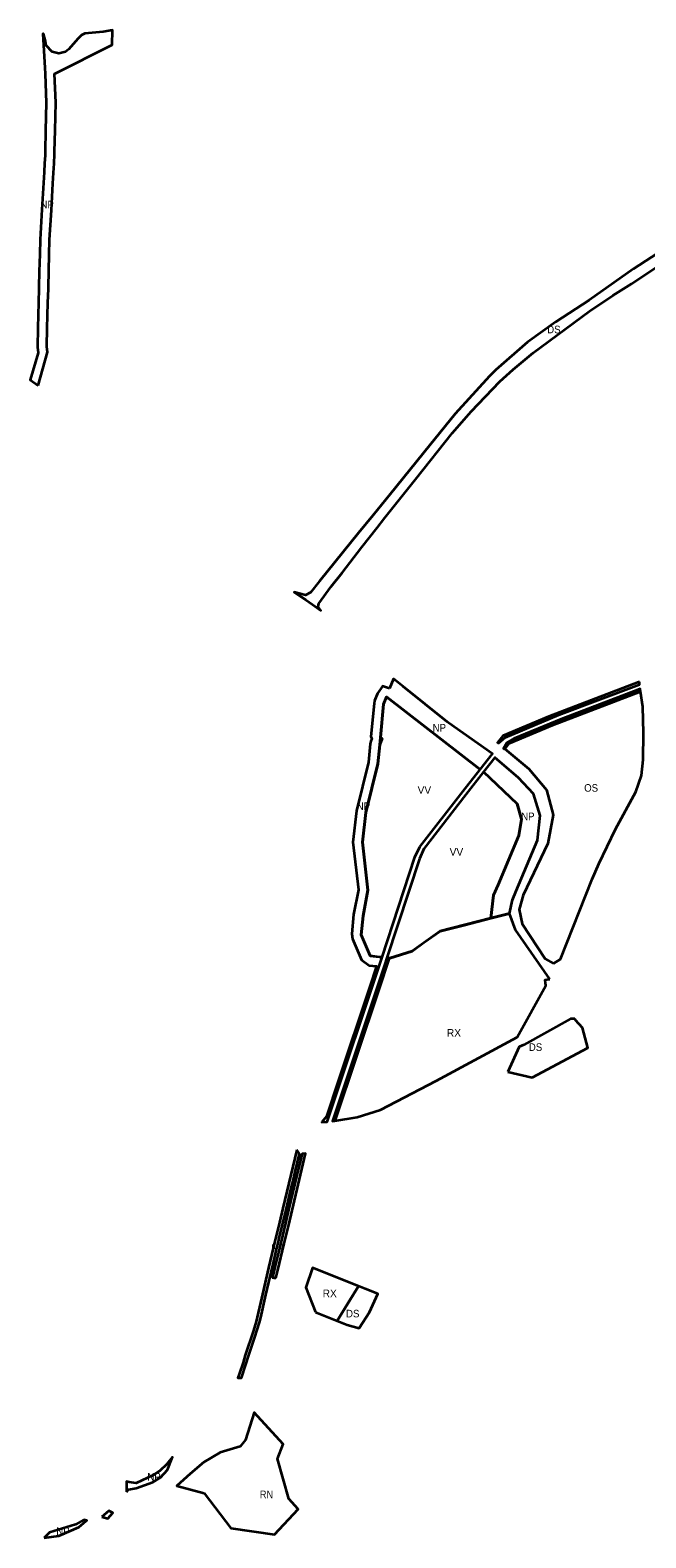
# Model space of a CAD drawing. Extents: x -650276 to -642489, y -1074311 to -1066658.
# Drawn here: x -649001 to -648027, y -1074311 to -1071929 of the extents above; entities that cross this region are included whole.
import ezdxf

# ---------------------------------------------------------------- set-up
doc = ezdxf.new("R2010")
doc.units = 0
doc.header["$LTSCALE"] = 4.8
for name, color, linetype, lineweight in [('24', 7, 'Continuous', 35), ('45', 7, 'Continuous', 35), ('48', 7, 'Continuous', 35), ('5', 7, 'Continuous', 35), ('7', 7, 'Continuous', 35), ('9', 7, 'Continuous', 35)]:
    doc.layers.add(name, color=color, linetype=linetype, lineweight=lineweight)
doc.layers.add('62', color=7, linetype='Continuous')
doc.layers.add('63', color=7, linetype='Continuous')

msp = doc.modelspace()

# ---------------------------------------------------------------- linework, layer by layer
at = {"layer": '24'}
msp.add_line((-648245.341, -1073575.152), (-648207, -1073584), dxfattribs=at)
for points in [[(-647942.21, -1072238.54), (-648046.69, -1072306.3), (-648117.12, -1072356), (-648169.81, -1072390.035), (-648214.73, -1072422.41), (-648264.618, -1072466.244), (-648274.53, -1072476.196), (-648328.847, -1072535.816), (-648369.37, -1072585.645), (-648431.557, -1072662.77), (-648459.243, -1072696.417), (-648481.468, -1072723.736), (-648543.255, -1072800.016), (-648557.588, -1072817.727), (-648565.726, -1072822.048), (-648583.407, -1072817.256), (-648564.86, -1072829.45), (-648554.22, -1072836.89), (-648541.102, -1072846.281), (-648545.462, -1072840.329), (-648544.632, -1072835.177), (-648524.979, -1072808.383), (-648507.503, -1072786.605), (-648476.204, -1072746.1), (-648452.274, -1072715.637), (-648439.912, -1072699.826), (-648391.796, -1072639.344), (-648333.178, -1072565.837), (-648303.791, -1072531.792), (-648258.165, -1072484.283), (-648237.406, -1072465.811), (-648205.298, -1072439.308), (-648116.32, -1072373.44), (-648079.76, -1072348.46), (-648050.276, -1072330.025), (-647969.894, -1072276.479)], [(-648139.56, -1073491.4), (-648146.4, -1073491.55), (-648220.42, -1073532.43), (-648227.63, -1073535.89), (-648245.341, -1073575.152)], [(-648207, -1073584), (-648119, -1073537), (-648127.31, -1073505.75), (-648138.41, -1073493.62), (-648139.56, -1073491.4)]]:
    msp.add_lwpolyline(points, dxfattribs=at)
msp.add_lwpolyline([(-648515.333, -1073968.584), (-648499.84, -1073974.76), (-648480.86, -1073980.25), (-648464.44, -1073954.69), (-648451.05, -1073925.87), (-648471, -1073918), (-648481.749, -1073913.76)], close=True, dxfattribs=at)
at = {"layer": '45'}
for points in [[(-648463.25, -1073392.125), (-648444.523, -1073394.235), (-648392.43, -1073235.98), (-648384.6, -1073219.54), (-648315.955, -1073131.889), (-648289.148, -1073097.66), (-648437.643, -1072982.601), (-648442.187, -1072994.5), (-648447.043, -1073046.967), (-648444.11, -1073048.69), (-648448.1, -1073058.393)], [(-648448.1, -1073058.393), (-648450.875, -1073088.375), (-648469.875, -1073165.5), (-648475.437, -1073212.375), (-648466.687, -1073288.25), (-648474.5, -1073328.75), (-648477.562, -1073358.875), (-648463.25, -1073392.125)], [(-648272.642, -1073332.558), (-648268, -1073296), (-648261, -1073280), (-648228, -1073202), (-648224, -1073176), (-648231, -1073152), (-648283.884, -1073101.15), (-648311.798, -1073137.127), (-648378.17, -1073222.67), (-648385.09, -1073238.58), (-648436.857, -1073395.099)], [(-648397.062, -1073384.375), (-648378.125, -1073370.875), (-648352.312, -1073353), (-648314.687, -1073343.25), (-648272.642, -1073332.558)], [(-648436.857, -1073395.099), (-648432.187, -1073395.625), (-648397.062, -1073384.375)]]:
    msp.add_lwpolyline(points, dxfattribs=at)
at = {"layer": '48'}
for points in [[(-648988.248, -1072491.089), (-648973.238, -1072438.27), (-648974.424, -1072429.462), (-648973.655, -1072400.254), (-648972.605, -1072360.164), (-648972.025, -1072338.183), (-648971.955, -1072335.341), (-648970.605, -1072283.823), (-648970.001, -1072260.788), (-648967.285, -1072213.663), (-648964.865, -1072171.684), (-648963.895, -1072154.905), (-648963.052, -1072140.301), (-648962.27, -1072125.223), (-648962.165, -1072120.949), (-648961.355, -1072088.12), (-648960.263, -1072043.893), (-648962.195, -1071998.309), (-648871.27, -1071952.643), (-648870.458, -1071929.441), (-648885.56, -1071932.1), (-648914.45, -1071934.78), (-648919.79, -1071937.27), (-648925.64, -1071943.18), (-648939.51, -1071959.25), (-648944.69, -1071963.44), (-648955.25, -1071966.15), (-648966.01, -1071963.74), (-648975.65, -1071953.47), (-648976.85, -1071944.78), (-648979.85, -1071935.11), (-648980.94, -1071935.12), (-648977.48, -1071989.2), (-648976.91, -1071998.2), (-648975.27, -1072044.01), (-648976.35, -1072087.75), (-648977.16, -1072120.58), (-648977.26, -1072124.65), (-648977.3, -1072126.08), (-648977.33, -1072127.34), (-648978.03, -1072139.48), (-648978.87, -1072154.04), (-648979.84, -1072170.82), (-648982.26, -1072212.8), (-648984.99, -1072260.16), (-648985.6, -1072283.43), (-648986.31, -1072310.66), (-648986.95, -1072334.96), (-648987.02, -1072337.8), (-648987.6, -1072359.77), (-648988.65, -1072399.86), (-648989.45, -1072430.27), (-648988.27, -1072439.04), (-649000.851, -1072482.138)], [(-648037.595, -1072959.123), (-648038.877, -1072959.418), (-648180.651, -1073013.629), (-648253.635, -1073044.348), (-648261.902, -1073054.939), (-648260.27, -1073056.17), (-648250.04, -1073047.08), (-648178.89, -1073017.03), (-648165.13, -1073011.22), (-648037.17, -1072963.24)], [(-648251.027, -1073065.418), (-648250.491, -1073064.698), (-648244.214, -1073056.657), (-648175.061, -1073027.551), (-648035.592, -1072974.222), (-648036.2, -1072969.98), (-648040.06, -1072971.47), (-648161.07, -1073017.9), (-648235.47, -1073048.4), (-648247.16, -1073055.34), (-648252.64, -1073064.13)], [(-648231, -1073152), (-648224, -1073176), (-648228, -1073202), (-648261, -1073280), (-648268, -1073296), (-648272.642, -1073332.558), (-648243.08, -1073325.04), (-648237.98, -1073303.4), (-648232.64, -1073289.31), (-648198.7, -1073209.08), (-648194.2, -1073170.13), (-648205.04, -1073136.07), (-648228.91, -1073110.54), (-648266.38, -1073078.59), (-648283.884, -1073101.15)], [(-648518.867, -1073652.836), (-648499.399, -1073594.679), (-648449.599, -1073445.278), (-648433.206, -1073395.51), (-648436.857, -1073395.099), (-648440.74, -1073406.84), (-648517.47, -1073637.26), (-648522.79, -1073653.23), (-648518.867, -1073652.836)], [(-648612.186, -1073900.905), (-648609.231, -1073888.415), (-648599.275, -1073846.445), (-648592.044, -1073816.692), (-648586.715, -1073794.059), (-648565.224, -1073704.393), (-648565.224, -1073704.393), (-648570.99, -1073704.56), (-648571.72, -1073707.63), (-648573.46, -1073714.88), (-648576.05, -1073725.82), (-648579.57, -1073740.47), (-648592.17, -1073793.18), (-648597.23, -1073814.32), (-648601.98, -1073834.2), (-648606.83, -1073854.48), (-648613.78, -1073883.59), (-648617.72, -1073900.06)], [(-648848.696, -1074238.993), (-648845.424, -1074235.305), (-648833.449, -1074232.685), (-648807.065, -1074223.704), (-648794.902, -1074216.219), (-648783.863, -1074204.056), (-648775.93, -1074183.91), (-648784.8, -1074195.26), (-648795.65, -1074205.35), (-648806.55, -1074212.62), (-648833.11, -1074225.2), (-648844.05, -1074223.24), (-648848.28, -1074222.49)], [(-648887.619, -1074278.134), (-648877.799, -1074280.64), (-648870.041, -1074271.932), (-648876.21, -1074268.73)], [(-648978.575, -1074311.426), (-648955.265, -1074308.325), (-648923.698, -1074294.313), (-648912.63, -1074284.912), (-648910.988, -1074284.211), (-648915.73, -1074283.08), (-648929.03, -1074290.14), (-648970.3, -1074302.9)]]:
    msp.add_lwpolyline(points, close=True, dxfattribs=at)
for points in [[(-648437.643, -1072982.601), (-648289.148, -1073097.66), (-648269.78, -1073072.93), (-648339.58, -1073023.82), (-648341.495, -1073022.285), (-648411.09, -1072966.5), (-648426.547, -1072954.108), (-648432.527, -1072969.463)], [(-648432.527, -1072969.463), (-648443.591, -1072965.983), (-648451.657, -1072977.25), (-648456.2, -1072989.149), (-648457.123, -1072993.118), (-648461.979, -1073045.585), (-648460.355, -1073048.753), (-648461.973, -1073052.688), (-648463.036, -1073057.011), (-648465.708, -1073085.876), (-648484.661, -1073162.812), (-648490.539, -1073212.35), (-648481.853, -1073287.675), (-648489.355, -1073326.567), (-648492.485, -1073357.358), (-648491.34, -1073364.805), (-648477.028, -1073398.055), (-648464.929, -1073407.031), (-648453.228, -1073408.349), (-648463.838, -1073440.559), (-648513.627, -1073589.927), (-648532.252, -1073645.567), (-648539.599, -1073654.802), (-648531.31, -1073654.08), (-648444.523, -1073394.235), (-648448.434, -1073393.794), (-648463.25, -1073392.125), (-648477.562, -1073358.875), (-648474.5, -1073328.75), (-648466.687, -1073288.25), (-648475.437, -1073212.375), (-648469.875, -1073165.5), (-648450.875, -1073088.375), (-648448.1, -1073058.393), (-648447.043, -1073046.967), (-648442.187, -1072994.5), (-648437.643, -1072982.601)], [(-648579.272, -1073698.648), (-648601.309, -1073790.592), (-648606.633, -1073813.202), (-648613.86, -1073842.943), (-648623.827, -1073884.957), (-648633.591, -1073926.228), (-648643.415, -1073969.782), (-648647.944, -1073983.639), (-648660.613, -1074022.822), (-648664.22, -1074034.155)], [(-648659.85, -1074037.72), (-648655.5, -1074024.36), (-648645.7, -1073994.3), (-648638.15, -1073971.13), (-648636.34, -1073963.19), (-648628.21, -1073927.61), (-648623.58, -1073907.34), (-648622.06, -1073901.02), (-648617.77, -1073883.09), (-648616.76, -1073878.91), (-648611.69, -1073857.74), (-648607.72, -1073841.19), (-648607.4, -1073839.84), (-648595.71, -1073791.1), (-648588.06, -1073759.19), (-648584.69, -1073745.15), (-648581.82, -1073733.14), (-648578.69, -1073720.11), (-648574.99, -1073704.67), (-648579.272, -1073698.648)], [(-648664.22, -1074034.155), (-648669.584, -1074051.005), (-648672.336, -1074058.391), (-648672.336, -1074058.391), (-648666.67, -1074058.64), (-648659.85, -1074037.72)]]:
    msp.add_lwpolyline(points, dxfattribs=at)
at = {"layer": '5'}
for points in [[(-648272.642, -1073332.558), (-648352.312, -1073353), (-648397.062, -1073384.375)], [(-648179.07, -1073428.81), (-648233.36, -1073350.68), (-648243.08, -1073325.04), (-648272.642, -1073332.558)], [(-648397.062, -1073384.375), (-648432.187, -1073395.625), (-648433.206, -1073395.51), (-648449.599, -1073445.278)], [(-648447.06, -1073635.39), (-648358.69, -1073589.35), (-648230.81, -1073520.18), (-648185.34, -1073438.91), (-648185.82, -1073435.12), (-648186.46, -1073430.01), (-648183.46, -1073429.52), (-648179.07, -1073428.81)], [(-648449.599, -1073445.278), (-648518.867, -1073652.836), (-648483.58, -1073646.7), (-648447.06, -1073635.39), (-648447.06, -1073635.39)]]:
    msp.add_lwpolyline(points, dxfattribs=at)
msp.add_lwpolyline([(-648549.76, -1073954.86), (-648515.333, -1073968.584), (-648498, -1073940), (-648481.749, -1073913.76), (-648554.42, -1073885.092), (-648564.75, -1073915.91)], close=True, dxfattribs=at)
at = {"layer": '7'}
msp.add_lwpolyline([(-648725.93, -1074240.58), (-648683.5, -1074296.12), (-648683.5, -1074296.12), (-648614.6, -1074306.17), (-648577.25, -1074266.06), (-648591.67, -1074249.72), (-648609.49, -1074186.61), (-648600.53, -1074163.47), (-648646.42, -1074113.19), (-648660.16, -1074156.75), (-648669.01, -1074167.27), (-648700.45, -1074176.73), (-648726.23, -1074192.02), (-648747.74, -1074210.12), (-648768.94, -1074229.25), (-648725.93, -1074240.58), (-648725.93, -1074240.58)], close=True, dxfattribs=at)
at = {"layer": '9'}
for points in [[(-648030.86, -1073039.71), (-648032.09, -1072998.65), (-648035.592, -1072974.222), (-648175.061, -1073027.551), (-648244.214, -1073056.657), (-648250.491, -1073064.698), (-648212.22, -1073096.39), (-648184.37, -1073129.89)], [(-648101.67, -1073246.63), (-648075.34, -1073191.93), (-648043.29, -1073132.97), (-648034.43, -1073107.07), (-648031.8, -1073082.07), (-648030.86, -1073039.71)], [(-648184.37, -1073129.89), (-648174.03, -1073168.94), (-648182.12, -1073214.56), (-648221.39, -1073296.24), (-648227.75, -1073318.75), (-648223.03, -1073341.59), (-648186.47, -1073396.47), (-648173.38, -1073404.03)], [(-648173.38, -1073404.03), (-648162.55, -1073397.4), (-648112.36, -1073270.87), (-648101.67, -1073246.63)]]:
    msp.add_lwpolyline(points, dxfattribs=at)

# ---------------------------------------------------------------- texts
at = {"layer": '62'}
for s, width, p in [('NP', 0.95, (-648984.583, -1072211.041)), ('NP', 0.95, (-648364.505, -1073037.594)), ('OS', 0.95, (-648124.882, -1073132.612)), ('NP', 0.95, (-648484.505, -1073161.594)), ('NP', 0.95, (-648224.505, -1073177.594)), ('DS', 0.95, (-648212.386, -1073542.148)), ('NP', 0.95, (-648619.524, -1073859.849)), ('DS', 0.95, (-648501.386, -1073963.148)), ('NP', 0.95, (-648815.524, -1074220.849)), ('RN', 0.9, (-648637.627, -1074248.756)), ('NP', 0.95, (-648959.524, -1074306.849))]:
    msp.add_text(s, height=12, dxfattribs=dict(at, width=width)).set_placement(p)
for s, p in [('VV', (-648388.203, -1073135.952)), ('VV', (-648337.553, -1073233.772)), ('RX', (-648341.882, -1073519.612)), ('RX', (-648538.32, -1073931.277))]:
    msp.add_text(s, height=12, dxfattribs=at).set_placement(p)
at = {"layer": '63', "width": 0.95}
msp.add_text('DS', height=12, dxfattribs=at).set_placement((-648183.378, -1072408.379))

doc.saveas('drawing.dxf')
